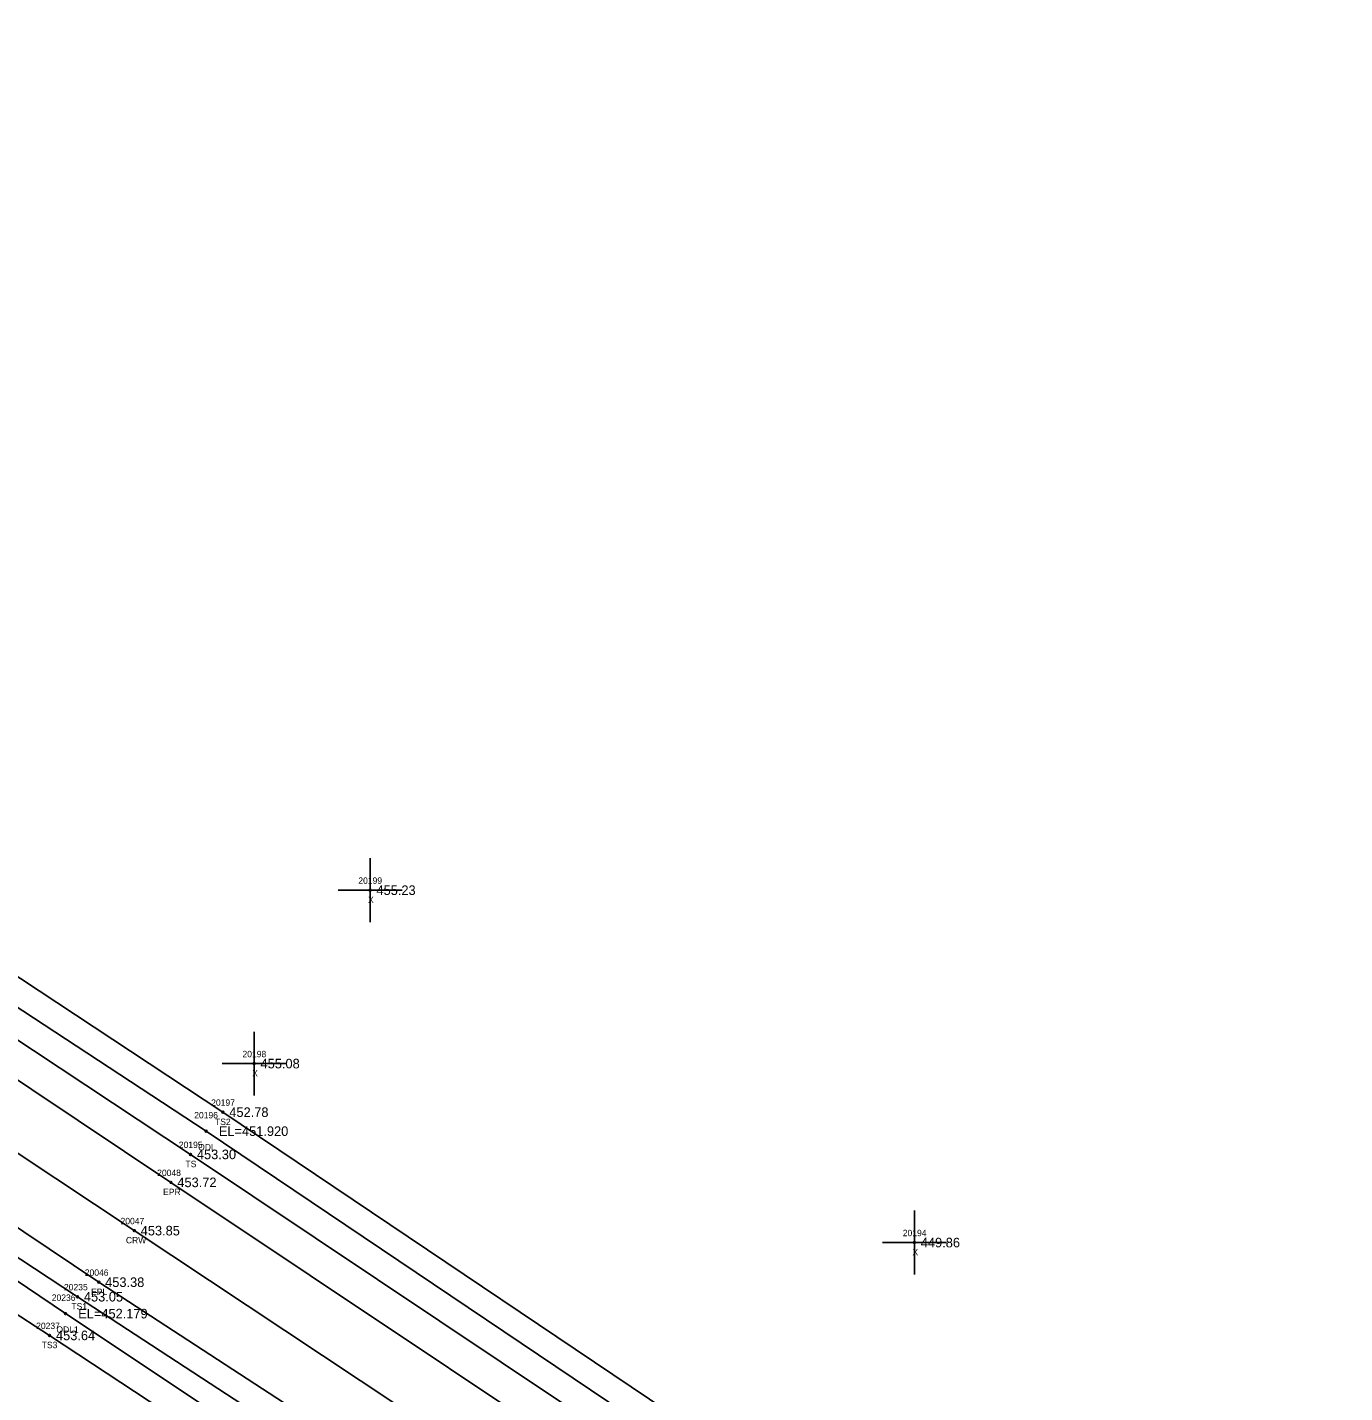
# Model space of a CAD drawing. Extents: x 1797709 to 1799052, y 896018 to 896955.
# Drawn here: x 1797995.4 to 1798201.7, y 896704.4 to 896918.3 of the extents above; entities that cross this region are included whole.
import ezdxf

# ---------------------------------------------------------------- set-up
doc = ezdxf.new("R2010")
doc.units = 0
for name, color, linetype in [('RD_DTM_BkLn1', 7, 'Continuous'), ('RD_DTM_BkLn2', 7, 'Continuous'), ('RD_DTM_BkLn_txCode', 7, 'Continuous'), ('RD_EX_H2O', 7, 'Continuous'), ('RD_EX_H2O_txCode', 7, 'Continuous'), ('RD_EX_Misc', 7, 'Continuous'), ('RD_EX_Misc_txCode', 7, 'Continuous'), ('RD_EX_Road', 7, 'Continuous'), ('RD_EX_Road_txCode', 7, 'Continuous'), ('RD_EX_TX_H2O_ELEV', 7, 'Continuous'), ('RD_EX_TX_Misc_ELEV', 7, 'Continuous'), ('RD_EX_TX_Road_ELEV', 7, 'Continuous'), ('RD_HC_Survey_ELEV', 7, 'Continuous'), ('RD_HC_Survey_txCode', 7, 'Continuous'), ('RD_SMD_Locator', 7, 'Continuous')]:
    doc.layers.add(name, color=color, linetype=linetype)

msp = doc.modelspace()

# ---------------------------------------------------------------- linework, layer by layer
at = {"layer": 'RD_DTM_BkLn1'}
msp.add_lwpolyline([(1798362.28, 896497.65), (1798275.53, 896555.51), (1798188.06, 896613.78), (1798100.6, 896671.09), (1798012.14, 896729.83), (1797925.7, 896787.19), (1797839.16, 896844.44), (1797754.21, 896899.34)], dxfattribs=at)
at = {"layer": 'RD_DTM_BkLn2'}
for points in [[(1798369.83, 896508.31), (1798367.91, 896513.92), (1798355.6, 896518.28), (1798283.49, 896566.57), (1798194.13, 896625.72), (1798108.66, 896683.13), (1798020.94, 896741.77), (1797934.88, 896798.69), (1797845.83, 896857.42), (1797757.7, 896918.3)], [(1798314.49, 896563.64), (1798288.01, 896573.8), (1798198.07, 896632.21), (1798113.28, 896689.71), (1798026.02, 896748.38), (1797939.51, 896805.48), (1797849.3, 896863.45), (1797757.7, 896918.3)], [(1798355.54, 896486.7), (1798350.74, 896485.38), (1798342.98, 896495.49), (1798267.09, 896545.1), (1798179.21, 896602.99), (1798092.54, 896661.13), (1798003.24, 896719.48), (1797918.21, 896775.43), (1797832.05, 896831.86), (1797744.82, 896887.66)], [(1798197.99, 896581.94), (1798175.06, 896597.9), (1798088.07, 896654.61), (1797998.87, 896713.42), (1797913.47, 896768.94), (1797829.42, 896827.1), (1797825.33, 896819.91), (1797827.32, 896807.68), (1797867.99, 896748.59)]]:
    msp.add_lwpolyline(points, dxfattribs=at)
at = {"layer": 'RD_EX_H2O'}
for points in [[(1798314.49, 896563.64), (1798286.18, 896571.49), (1798196.7, 896629.98), (1798111.06, 896686.41), (1798023.38, 896745.41), (1797937.01, 896802.03), (1797847.56, 896860.46), (1797757.7, 896918.3)], [(1798197.99, 896581.94), (1798176.34, 896599.45), (1798090.08, 896657.76), (1798001.35, 896716.83), (1797917.02, 896773.77), (1797830.54, 896829.07), (1797814.36, 896825.45)]]:
    msp.add_lwpolyline(points, dxfattribs=at)
at = {"layer": 'RD_EX_Misc'}
for p, q in [((1798049.07, 896778.15), (1798049.07, 896788.15)), ((1798044.07, 896783.15), (1798054.07, 896783.15)), ((1798030.91, 896750.99), (1798030.91, 896760.99)), ((1798025.91, 896755.99), (1798035.91, 896755.99)), ((1798134.34, 896722.96), (1798134.34, 896732.96)), ((1798129.34, 896727.96), (1798139.34, 896727.96))]:
    msp.add_line(p, q, dxfattribs=at)
at = {"layer": 'RD_EX_Road'}
for points in [[(1798362.28, 896497.65), (1798367.54, 896505.07), (1798280.71, 896562.69), (1798193.2, 896621.02), (1798104.98, 896679.23), (1798017.88, 896737.39), (1797930.72, 896795.63), (1797844.07, 896853.07), (1797758.11, 896906.97)], [(1798362.28, 896497.65), (1798357.85, 896490.18), (1798271.29, 896548.71), (1798183.2, 896606.17), (1798096.06, 896663.44), (1798006.57, 896721.75), (1797920.8, 896779.27), (1797834.41, 896836.87), (1797748.77, 896891.01)]]:
    msp.add_lwpolyline(points, dxfattribs=at)
at = {"layer": 'RD_SMD_Locator'}
for centre in [(1798049.07, 896783.15), (1798030.91, 896755.99), (1798026.02, 896748.38), (1798023.38, 896745.41), (1798020.94, 896741.77), (1798017.88, 896737.39), (1798012.14, 896729.83), (1798134.34, 896727.96), (1798006.57, 896721.75), (1798003.24, 896719.48), (1798001.35, 896716.83), (1797998.87, 896713.42)]:
    msp.add_circle(centre, 0.15, dxfattribs=at)

# ---------------------------------------------------------------- texts
at = {"layer": 'RD_DTM_BkLn_txCode'}
for s, p in [('20197', (1798024.18, 896749.38)), ('TS2', (1798024.78, 896746.38)), ('20195', (1798019.11, 896742.77)), ('TS', (1798020.15, 896739.77)), ('20235', (1798001.12, 896720.48)), ('TS1', (1798002.28, 896717.48)), ('20237', (1797996.76, 896714.42)), ('TS3', (1797997.63, 896711.42))]:
    msp.add_text(s, height=1, dxfattribs=at).set_placement(p)
at = {"layer": 'RD_EX_H2O_txCode'}
for s, p in [('20196', (1798021.52, 896747.41)), ('ODL', (1798022.14, 896742.41)), ('20236', (1797999.21, 896718.83)), ('ODL1', (1797999.94, 896713.83))]:
    msp.add_text(s, height=1, dxfattribs=at).set_placement(p)
at = {"layer": 'RD_EX_Misc_txCode'}
for s, p in [('20199', (1798047.23, 896784.15)), ('X', (1798048.75, 896781.15)), ('20198', (1798029.08, 896756.99)), ('X', (1798030.6, 896753.99)), ('20194', (1798132.51, 896728.96)), ('X', (1798134.03, 896725.96))]:
    msp.add_text(s, height=1, dxfattribs=at).set_placement(p)
at = {"layer": 'RD_EX_Road_txCode'}
for s, p in [('20048', (1798015.72, 896738.39)), ('EPR', (1798016.65, 896735.39)), ('20046', (1798004.38, 896722.75)), ('EPL', (1798005.36, 896719.75))]:
    msp.add_text(s, height=1, dxfattribs=at).set_placement(p)
at = {"layer": 'RD_EX_TX_H2O_ELEV'}
for s, p in [('EL=451.920', (1798025.38, 896744.66)), ('EL=452.179', (1798003.35, 896716.08))]:
    msp.add_text(s, height=1.5, dxfattribs=at).set_placement(p)
at = {"layer": 'RD_EX_TX_Misc_ELEV'}
for s, p in [('455.23', (1798050.07, 896782.4)), ('455.08', (1798031.91, 896755.24)), ('452.78', (1798027.02, 896747.63)), ('453.30', (1798021.94, 896741.02)), ('449.86', (1798135.34, 896727.21)), ('453.05', (1798004.24, 896718.73)), ('453.64', (1797999.87, 896712.67))]:
    msp.add_text(s, height=1.5, dxfattribs=at).set_placement(p)
at = {"layer": 'RD_EX_TX_Road_ELEV'}
for s, p in [('453.72', (1798018.88, 896736.64)), ('453.38', (1798007.57, 896721))]:
    msp.add_text(s, height=1.5, dxfattribs=at).set_placement(p)
at = {"layer": 'RD_HC_Survey_ELEV'}
msp.add_text('453.85', height=1.5, dxfattribs=at).set_placement((1798013.14, 896729.08))
at = {"layer": 'RD_HC_Survey_txCode'}
for s, p in [('20047', (1798009.98, 896730.83)), ('CRW', (1798010.82, 896727.83))]:
    msp.add_text(s, height=1, dxfattribs=at).set_placement(p)

doc.saveas('drawing.dxf')
